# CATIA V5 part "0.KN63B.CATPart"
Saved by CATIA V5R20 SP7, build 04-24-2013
Part number: 0.KN63B
Material "Nessuno"
Bounding box of the stored display mesh (mm): x -30.572 to 149.213, y -143.683 to 0, z -56.919 to 41.584
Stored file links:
  C:\Users\designer2\Desktop\Ottobre 2022\25-10-2022\04\Yori Evo 48V\0.KN63B.CATPart
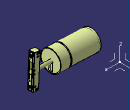
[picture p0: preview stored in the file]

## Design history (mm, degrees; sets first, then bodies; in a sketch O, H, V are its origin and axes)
AxisSystem1: origin (0, 0, 0), X (1, 0, 0), Y (0, 1, 0), Z (0, 0, 1)
Set1
  DatumSurface1
Body1 (main body), material "Nessuno"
